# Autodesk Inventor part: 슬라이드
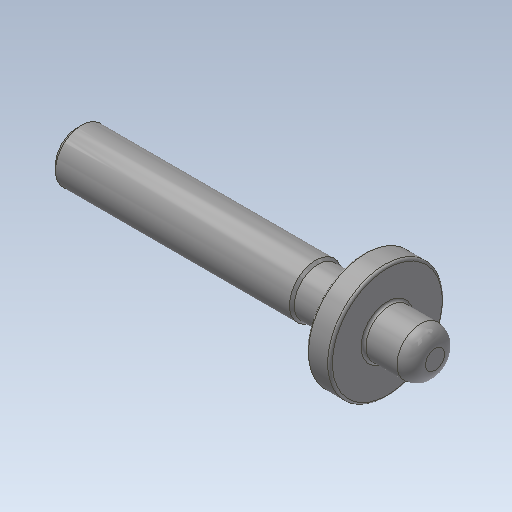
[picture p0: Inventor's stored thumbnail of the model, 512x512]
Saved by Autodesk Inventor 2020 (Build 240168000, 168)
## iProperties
Created: 2015-12
Part Number: 슬라이드
Document SubType Name: Modeling
Designer: mdu
Density: 7.86 g/cm^3
Mass: 66.9288 g
Surface Area: 35.5023 cm^2
Volume: 8.51511 cm^3
Material: 강철, 연강
Appearance: 강철
Company: 한국ATC센터
Author: mdu
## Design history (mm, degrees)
sketch "스케치1"
  geometry: L1 (-32.5, 0)-(32.5, 0); L2 (32.5, 0)-(32.5, 12); L3 (32.5, 12)-(27.5, 12); L4 (27.5, 12)-(27.5, 5); L5 (27.5, 5)-(18, 5); L6 (18, 5)-(17.5, 5.5); L7 (17.5, 5.5)-(-32.5, 5.5); L8 (-32.5, 5.5)-(-32.5, 0); 1 further point
  constraints: 16 end point, 4 parallel, 2 midpoint, 2 perpendicular, 1 horizontal
  dimensions: "d0" = 65 distance of L1.start L1.end; "d1" = 11 diameter of L7 L1; "d2" = 24 diameter of L3 L1; "d3" = 5 distance of L2.end L3.end; "d4" = 10 diameter of L5 L1; "d5" = 135 deg angle of L6 L5; "d6" = 15 distance from line of L2 L6.end
revolve "회전1" sketch "스케치1" stored, may be unused: angle "d7" = 90 deg
chamfer "모따기1" distance "d8" = 1; stored, may be unused: second distance "d9" = 2, angle "d10" = 45 deg
fillet "모깎기1" dims "d11" = 0.5
sketch "스케치2"
  geometry: C1 r 11.5 at (0, 0) reference; C2 r 5 at (0, 0)
  constraints: 1 centre point, 1 coincident
  dimensions: "d12" = 10 diameter of C2
extrude "돌출1" join sketch "스케치2" distance "d13" = 10; taper "d14" = 0 deg
fillet "모깎기2" dims "d16" = 0.5
fillet "모깎기3" dims "d17" = 3
node "솔리드1"
